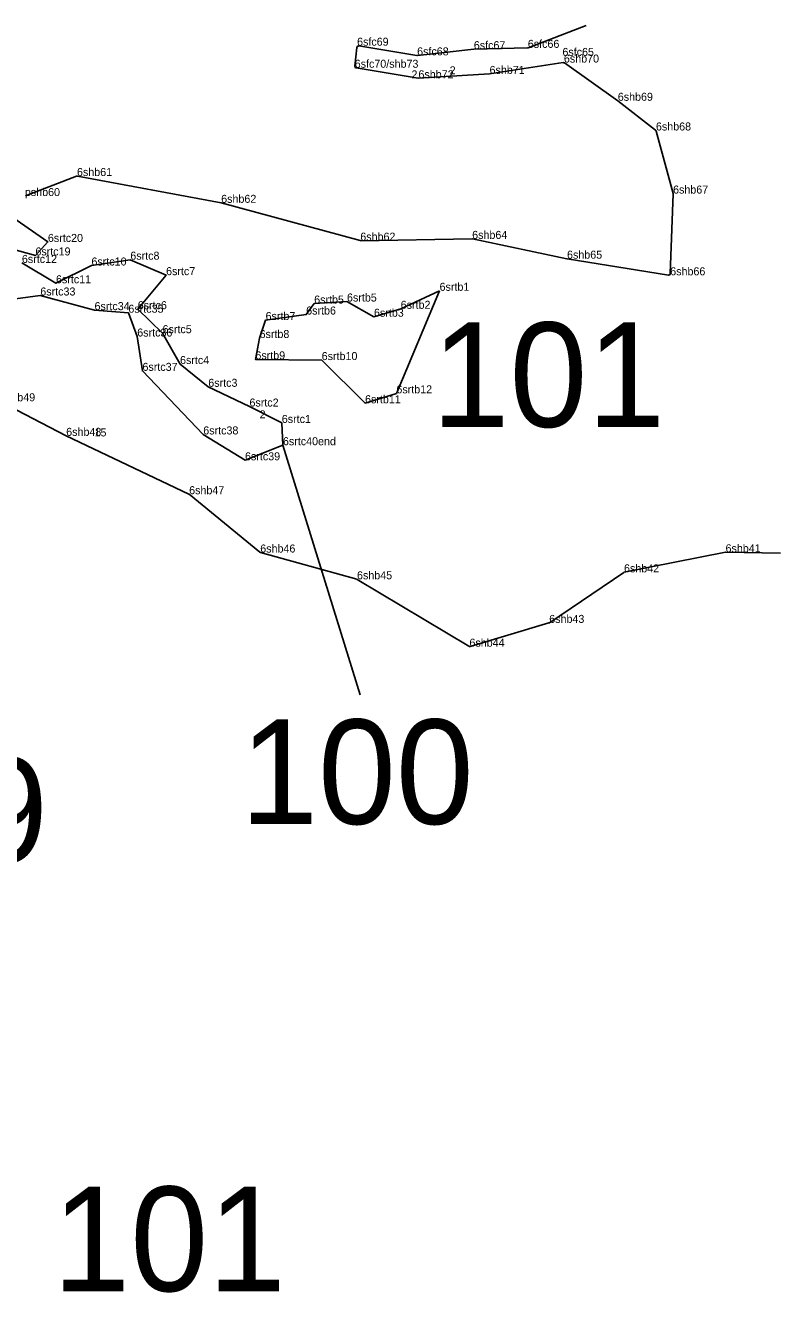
# Model space of a CAD drawing. Extents: x 2072529 to 2268812, y 436423 to 470008.
# Drawn here: x 2138284 to 2138755, y 442677 to 443469 of the extents above; entities that cross this region are included whole.
import ezdxf

# ---------------------------------------------------------------- set-up
doc = ezdxf.new("R2010")
doc.units = 0
for name, color, linetype in [('Old_Level_10', 7, 'Continuous'), ('Old_Level_20', 7, 'Continuous'), ('Old_Level_60', 7, 'Continuous'), ('Old_Level_62', 7, 'Continuous')]:
    doc.layers.add(name, color=color, linetype=linetype)

msp = doc.modelspace()

# ---------------------------------------------------------------- linework, layer by layer
at = {"layer": 'Old_Level_10'}
for p, q in [((2138597.623, 443454.634), (2138633.947, 443468.642)), ((2138597.623, 443454.634), (2138633.947, 443468.642)), ((2138597.623, 443454.634), (2138633.947, 443468.642)), ((2138489.421, 443443.084), (2138490.671, 443454.867)), ((2138489.421, 443443.084), (2138490.671, 443454.867)), ((2138489.421, 443443.084), (2138490.671, 443454.867)), ((2138491.824, 443455.749), (2138528.173, 443449.896)), ((2138491.824, 443455.749), (2138528.173, 443449.896)), ((2138491.824, 443455.749), (2138528.173, 443449.896)), ((2138528.44, 443449.89), (2138563.678, 443453.732)), ((2138528.44, 443449.89), (2138563.678, 443453.732)), ((2138528.44, 443449.89), (2138563.678, 443453.732)), ((2138563.762, 443453.738), (2138597.288, 443454.568)), ((2138563.762, 443453.738), (2138597.288, 443454.568)), ((2138563.762, 443453.738), (2138597.288, 443454.568)), ((2138619.594, 443445.326), (2138573.599, 443438.292)), ((2138619.594, 443445.326), (2138573.599, 443438.292)), ((2138619.594, 443445.326), (2138573.599, 443438.292)), ((2138653.641, 443421.521), (2138620.324, 443445.153)), ((2138653.641, 443421.521), (2138620.324, 443445.153)), ((2138653.641, 443421.521), (2138620.324, 443445.153)), ((2138529.02, 443435.572), (2138490.252, 443441.992)), ((2138529.02, 443435.572), (2138490.252, 443441.992)), ((2138529.02, 443435.572), (2138490.252, 443441.992)), ((2138573.509, 443438.282), (2138529.245, 443435.56)), ((2138573.509, 443438.282), (2138529.245, 443435.56)), ((2138573.509, 443438.282), (2138529.245, 443435.56)), ((2138677.219, 443403.145), (2138653.677, 443421.494)), ((2138677.219, 443403.145), (2138653.677, 443421.494)), ((2138677.219, 443403.145), (2138653.677, 443421.494)), ((2138688.148, 443363.661), (2138677.569, 443402.618)), ((2138688.148, 443363.661), (2138677.569, 443402.618)), ((2138688.148, 443363.661), (2138677.569, 443402.618)), ((2138283.574, 443362.081), (2138315.566, 443374.382)), ((2138283.574, 443362.081), (2138315.566, 443374.382)), ((2138283.574, 443362.081), (2138315.566, 443374.382)), ((2138316.108, 443374.431), (2138405.857, 443357.737)), ((2138316.108, 443374.431), (2138405.857, 443357.737)), ((2138316.108, 443374.431), (2138405.857, 443357.737)), ((2138686.442, 443313.574), (2138688.183, 443363.364)), ((2138686.442, 443313.574), (2138688.183, 443363.364)), ((2138686.442, 443313.574), (2138688.183, 443363.364)), ((2138405.936, 443357.719), (2138492.673, 443334.121)), ((2138405.936, 443357.719), (2138492.673, 443334.121)), ((2138405.936, 443357.719), (2138492.673, 443334.121)), ((2138492.952, 443334.086), (2138562.59, 443335.188)), ((2138492.952, 443334.086), (2138562.59, 443335.188)), ((2138492.952, 443334.086), (2138562.59, 443335.188)), ((2138562.81, 443335.167), (2138621.919, 443322.834)), ((2138562.81, 443335.167), (2138621.919, 443322.834)), ((2138562.81, 443335.167), (2138621.919, 443322.834)), ((2138621.964, 443322.825), (2138685.283, 443312.621)), ((2138621.964, 443322.825), (2138685.283, 443312.621)), ((2138621.964, 443322.825), (2138685.283, 443312.621)), ((2138309.078, 443212.116), (2138267.916, 443233.645)), ((2138309.078, 443212.116), (2138267.916, 443233.645)), ((2138309.078, 443212.116), (2138267.916, 443233.645)), ((2138385.793, 443175.702), (2138309.112, 443212.099)), ((2138385.793, 443175.702), (2138309.112, 443212.099)), ((2138385.793, 443175.702), (2138309.112, 443212.099)), ((2138430.144, 443139.331), (2138385.999, 443175.571)), ((2138430.144, 443139.331), (2138385.999, 443175.571)), ((2138430.144, 443139.331), (2138385.999, 443175.571)), ((2138490.623, 443122.516), (2138430.512, 443139.141)), ((2138490.623, 443122.516), (2138430.512, 443139.141)), ((2138490.623, 443122.516), (2138430.512, 443139.141)), ((2138720.874, 443139.332), (2138657.738, 443126.878)), ((2138720.874, 443139.332), (2138657.738, 443126.878)), ((2138720.874, 443139.332), (2138657.738, 443126.878)), ((2138755.383, 443138.845), (2138721.082, 443139.35)), ((2138755.383, 443138.845), (2138721.082, 443139.35)), ((2138755.383, 443138.845), (2138721.082, 443139.35)), ((2138657.371, 443126.725), (2138610.949, 443095.315)), ((2138657.371, 443126.725), (2138610.949, 443095.315)), ((2138657.371, 443126.725), (2138610.949, 443095.315)), ((2138560.615, 443080.6), (2138490.871, 443122.41)), ((2138560.615, 443080.6), (2138490.871, 443122.41)), ((2138560.615, 443080.6), (2138490.871, 443122.41)), ((2138610.675, 443095.185), (2138561.415, 443080.5)), ((2138610.675, 443095.185), (2138561.415, 443080.5)), ((2138610.675, 443095.185), (2138561.415, 443080.5))]:
    msp.add_line(p, q, dxfattribs=at)
for points in [[(2138260.342, 443332.899), (2138289.85, 443324.861), (2138297.655, 443333.293), (2138261.088, 443358.613)], [(2138353.775, 443291.267), (2138371.484, 443312.536), (2138349.149, 443322.198), (2138324.855, 443318.568), (2138302.713, 443307.466), (2138281.416, 443320.168)], [(2138249.574, 443294.054), (2138292.913, 443299.825), (2138326.784, 443290.664), (2138347.931, 443289.061), (2138353.466, 443274.177), (2138356.738, 443252.74), (2138394.714, 443213.003), (2138420.788, 443196.837), (2138444.474, 443206.263)], [(2138444.474, 443206.263), (2138443.773, 443220.176), (2138423.578, 443230.428), (2138397.845, 443242.769), (2138380.197, 443256.982), (2138369.287, 443276.261), (2138353.775, 443291.267)]]:
    msp.add_lwpolyline(points, dxfattribs=at)
msp.add_lwpolyline([(2138542.331, 443302.749), (2138518.058, 443291.525), (2138501.344, 443286.554), (2138484.495, 443296.056), (2138464.007, 443294.778), (2138459.011, 443287.92), (2138433.642, 443284.487), (2138429.887, 443273.263), (2138427.279, 443259.903), (2138468.686, 443259.469), (2138495.764, 443232.49), (2138515.353, 443238.67)], close=True, dxfattribs=at)
for centre, start, end in [((2138491.665, 443454.762), 80.852919, 173.944), ((2138491.665, 443454.762), 80.852919, 173.944), ((2138491.665, 443454.762), 80.852919, 173.944), ((2138563.787, 443452.738), 91.417628, 96.223678), ((2138563.787, 443452.738), 91.417628, 96.223678), ((2138563.787, 443452.738), 91.417628, 96.223678), ((2138597.263, 443455.567), 271.417628, 291.088622), ((2138597.263, 443455.567), 271.417628, 291.088622), ((2138597.263, 443455.567), 271.417628, 291.088622), ((2138490.415, 443442.978), 173.944, 260.596733), ((2138490.415, 443442.978), 173.944, 260.596733), ((2138490.415, 443442.978), 173.944, 260.596733), ((2138528.332, 443450.884), 260.852919, 276.223678), ((2138528.332, 443450.884), 260.852919, 276.223678), ((2138528.332, 443450.884), 260.852919, 276.223678), ((2138619.745, 443444.337), 54.651453, 98.694794), ((2138619.745, 443444.337), 54.651453, 98.694794), ((2138619.745, 443444.337), 54.651453, 98.694794), ((2138529.184, 443436.558), 260.596736, 273.519319), ((2138529.184, 443436.558), 260.596736, 273.519319), ((2138529.184, 443436.558), 260.596736, 273.519319), ((2138573.448, 443439.28), 273.519319, 278.694794), ((2138573.448, 443439.28), 273.519319, 278.694794), ((2138573.448, 443439.28), 273.519319, 278.694794), ((2138653.062, 443420.705), 52.066619, 54.651453), ((2138653.062, 443420.705), 52.066619, 54.651453), ((2138653.062, 443420.705), 52.066619, 54.651453), ((2138676.604, 443402.356), 15.192508, 52.066619), ((2138676.604, 443402.356), 15.192508, 52.066619), ((2138676.604, 443402.356), 15.192508, 52.066619), ((2138315.925, 443373.448), 79.463061, 111.031378), ((2138315.925, 443373.448), 79.463061, 111.031378), ((2138315.925, 443373.448), 79.463061, 111.031378), ((2138687.183, 443363.399), 357.997247, 15.192508), ((2138687.183, 443363.399), 357.997247, 15.192508), ((2138687.183, 443363.399), 357.997247, 15.192508), ((2138405.674, 443356.754), 74.780197, 79.463061), ((2138405.674, 443356.754), 74.780197, 79.463061), ((2138405.674, 443356.754), 74.780197, 79.463061), ((2138492.936, 443335.086), 254.780197, 270.906611), ((2138492.936, 443335.086), 254.780197, 270.906611), ((2138492.936, 443335.086), 254.780197, 270.906611), ((2138562.606, 443334.188), 78.213789, 90.906608), ((2138562.606, 443334.188), 78.213789, 90.906608), ((2138562.606, 443334.188), 78.213789, 90.906608), ((2138622.123, 443323.813), 258.213792, 260.845394), ((2138622.123, 443323.813), 258.213792, 260.845394), ((2138622.123, 443323.813), 258.213792, 260.845394), ((2138685.442, 443313.609), 260.845394, 357.997247), ((2138685.442, 443313.609), 260.845394, 357.997247), ((2138685.442, 443313.609), 260.845394, 357.997247), ((2138309.541, 443213.002), 242.388897, 244.608275), ((2138309.541, 443213.002), 242.388897, 244.608275), ((2138309.541, 443213.002), 242.388897, 244.608275), ((2138385.364, 443174.798), 50.616844, 64.608275), ((2138385.364, 443174.798), 50.616844, 64.608275), ((2138385.364, 443174.798), 50.616844, 64.608275), ((2138430.779, 443140.104), 230.616844, 254.540636), ((2138430.779, 443140.104), 230.616844, 254.540636), ((2138430.779, 443140.104), 230.616844, 254.540636), ((2138721.067, 443138.351), 89.155339, 101.158225), ((2138721.067, 443138.351), 89.155339, 101.158225), ((2138721.067, 443138.351), 89.155339, 101.158225), ((2138657.931, 443125.897), 101.158222, 124.083356), ((2138657.931, 443125.897), 101.158222, 124.083356), ((2138657.931, 443125.897), 101.158222, 124.083356), ((2138490.356, 443121.552), 59.058681, 74.540636), ((2138490.356, 443121.552), 59.058681, 74.540636), ((2138490.356, 443121.552), 59.058681, 74.540636), ((2138610.389, 443096.143), 286.600347, 304.083356), ((2138610.389, 443096.143), 286.600347, 304.083356), ((2138610.389, 443096.143), 286.600347, 304.083356), ((2138561.129, 443081.458), 239.058681, 286.600347), ((2138561.129, 443081.458), 239.058681, 286.600347), ((2138561.129, 443081.458), 239.058681, 286.600347)]:
    msp.add_arc(centre, 1, start, end, dxfattribs=at)
at = {"layer": 'Old_Level_20'}
for p, q in [((2138490.782, 443455.917), (2138490.782, 443455.917)), ((2138563.72, 443453.737), (2138563.72, 443453.737)), ((2138597.461, 443454.572), (2138597.461, 443454.572)), ((2138528.306, 443449.875), (2138528.306, 443449.875)), ((2138619.066, 443449.531), (2138619.066, 443449.531)), ((2138619.994, 443445.387), (2138619.994, 443445.387)), ((2138489.321, 443442.146), (2138489.321, 443442.146)), ((2138529.132, 443435.553), (2138529.132, 443435.553)), ((2138573.554, 443438.285), (2138573.554, 443438.285)), ((2138653.659, 443421.508), (2138653.659, 443421.508)), ((2138677.482, 443402.94), (2138677.482, 443402.94)), ((2138315.83, 443374.483), (2138315.83, 443374.483)), ((2138688.188, 443363.515), (2138688.188, 443363.515)), ((2138405.897, 443357.73), (2138405.897, 443357.73)), ((2138297.655, 443333.293), (2138297.655, 443333.293)), ((2138492.81, 443334.084), (2138492.81, 443334.084)), ((2138562.701, 443335.19), (2138562.701, 443335.19)), ((2138289.85, 443324.861), (2138289.85, 443324.861)), ((2138324.855, 443318.568), (2138324.855, 443318.568)), ((2138349.149, 443322.198), (2138349.149, 443322.198)), ((2138621.941, 443322.829), (2138621.941, 443322.829)), ((2138371.484, 443312.536), (2138371.484, 443312.536)), ((2138686.402, 443312.441), (2138686.402, 443312.441)), ((2138302.713, 443307.466), (2138302.713, 443307.466)), ((2138542.331, 443302.749), (2138542.331, 443302.749)), ((2138292.913, 443299.825), (2138292.913, 443299.825)), ((2138464.007, 443294.778), (2138464.007, 443294.778)), ((2138484.495, 443296.056), (2138484.495, 443296.056)), ((2138326.784, 443290.664), (2138326.784, 443290.664)), ((2138347.931, 443289.061), (2138347.931, 443289.061)), ((2138353.775, 443291.267), (2138353.775, 443291.267)), ((2138433.642, 443284.487), (2138433.642, 443284.487)), ((2138459.011, 443287.92), (2138459.011, 443287.92)), ((2138501.344, 443286.554), (2138501.344, 443286.554)), ((2138518.058, 443291.525), (2138518.058, 443291.525)), ((2138369.287, 443276.261), (2138369.287, 443276.261)), ((2138353.466, 443274.177), (2138353.466, 443274.177)), ((2138429.887, 443273.263), (2138429.887, 443273.263)), ((2138356.738, 443252.74), (2138356.738, 443252.74)), ((2138380.197, 443256.982), (2138380.197, 443256.982)), ((2138427.279, 443259.903), (2138427.279, 443259.903)), ((2138468.686, 443259.469), (2138468.686, 443259.469)), ((2138397.845, 443242.769), (2138397.845, 443242.769)), ((2138515.353, 443238.67), (2138515.353, 443238.67)), ((2138423.578, 443230.428), (2138423.578, 443230.428)), ((2138495.764, 443232.49), (2138495.764, 443232.49)), ((2138394.714, 443213.003), (2138394.714, 443213.003)), ((2138443.773, 443220.176), (2138443.773, 443220.176)), ((2138309.095, 443212.107), (2138309.095, 443212.107)), ((2138444.474, 443206.263), (2138444.474, 443206.263)), ((2138420.788, 443196.837), (2138420.788, 443196.837)), ((2138385.904, 443175.649), (2138385.904, 443175.649)), ((2138430.308, 443139.197), (2138430.308, 443139.197)), ((2138720.977, 443139.352), (2138720.977, 443139.352)), ((2138656.989, 443127.017), (2138656.989, 443127.017)), ((2138656.989, 443127.017), (2138656.989, 443127.017)), ((2138657.539, 443126.839), (2138657.539, 443126.839)), ((2138490.754, 443122.48), (2138490.754, 443122.48)), ((2138610.822, 443095.229), (2138610.822, 443095.229)), ((2138560.993, 443080.374), (2138560.993, 443080.374))]:
    msp.add_line(p, q, dxfattribs=at)
at = {"layer": 'Old_Level_62'}
msp.add_line((2138492.764, 443050.36), (2138444.474, 443206.263), dxfattribs=at)

# ---------------------------------------------------------------- texts
at = {"layer": 'Old_Level_60'}
for s, p in [('6sfc69', (2138490.782, 443455.917)), ('6sfc67', (2138563.72, 443453.737)), ('6sfc66', (2138597.461, 443454.572)), ('6sfc68', (2138528.306, 443449.875)), ('6sfc65', (2138619.066, 443449.531)), ('6shb70', (2138619.994, 443445.387)), ('6sfc70/shb73', (2138489.321, 443442.146)), ('2', (2138548.627, 443438.014)), ('6shb71', (2138573.554, 443438.285)), ('2', (2138524.788, 443435.486)), ('6shb72', (2138529.132, 443435.553)), ('6shb69', (2138653.659, 443421.508)), ('6shb68', (2138677.482, 443402.94)), ('6shb61', (2138315.83, 443374.483)), ('pshb60', (2138283.278, 443361.967)), ('6shb67', (2138688.188, 443363.515)), ('6shb62', (2138405.897, 443357.73)), ('6shb64', (2138562.701, 443335.19)), ('6srtc20', (2138297.655, 443333.293)), ('6shb62', (2138492.81, 443334.084)), ('6srtc12', (2138281.416, 443320.168)), ('6srtc19', (2138289.85, 443324.861)), ('6srtc8', (2138349.149, 443322.198)), ('6shb65', (2138621.941, 443322.829)), ('6srtc10', (2138324.855, 443318.568)), ('6srtc7', (2138371.484, 443312.536)), ('6shb66', (2138686.402, 443312.441)), ('6srtc11', (2138302.713, 443307.466)), ('6srtb1', (2138542.331, 443302.749)), ('6srtc33', (2138292.913, 443299.825)), ('6srtb5', (2138464.007, 443294.778)), ('6srtb5', (2138484.495, 443296.056)), ('6srtc34', (2138326.784, 443290.664)), ('6srtc35', (2138347.931, 443289.061)), ('6srtc6', (2138353.775, 443291.267)), ('6srtb6', (2138459.011, 443287.92)), ('6srtb2', (2138518.058, 443291.525)), ('6srtb7', (2138433.642, 443284.487)), ('6srtb3', (2138501.344, 443286.554)), ('6srtc36', (2138353.466, 443274.177)), ('6srtc5', (2138369.287, 443276.261)), ('6srtb8', (2138429.887, 443273.263)), ('6srtc4', (2138380.197, 443256.982)), ('6srtb9', (2138427.279, 443259.903)), ('6srtb10', (2138468.686, 443259.469)), ('6srtc37', (2138356.738, 443252.74)), ('6srtc3', (2138397.845, 443242.769)), ('6shb49', (2138267.765, 443233.724)), ('6srtb11', (2138495.764, 443232.49)), ('6srtb12', (2138515.353, 443238.67)), ('6srtc2', (2138423.578, 443230.428)), ('2', (2138429.887, 443223.065)), ('6srtc1', (2138443.773, 443220.176)), ('6shb48', (2138309.095, 443212.107)), ('15', (2138326.784, 443211.755)), ('6srtc38', (2138394.714, 443213.003)), ('6srtc40end', (2138444.474, 443206.263)), ('6srtc39', (2138420.788, 443196.837)), ('6shb47', (2138385.904, 443175.649)), ('6shb46', (2138430.308, 443139.197)), ('6shb41', (2138720.977, 443139.352)), ('6shb45', (2138490.754, 443122.48)), ('6shb42', (2138657.539, 443126.839)), ('6shb43', (2138610.822, 443095.229)), ('6shb44', (2138560.993, 443080.374))]:
    msp.add_text(s, height=5, dxfattribs=at).set_placement(p)
at = {"layer": 'Old_Level_62'}
for s, p in [('101', (2138537.46, 443217.666)), ('100', (2138417.856, 442969.523)), ('99', (2138200.482, 442945.709)), ('101', (2138300.553, 442677.623))]:
    msp.add_text(s, height=65.34, dxfattribs=at).set_placement(p)

doc.saveas('drawing.dxf')
